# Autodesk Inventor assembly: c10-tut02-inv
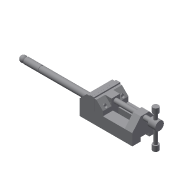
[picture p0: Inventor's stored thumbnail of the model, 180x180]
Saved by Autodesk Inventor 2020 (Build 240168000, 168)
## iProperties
Created: 2009-05
Part Number: c10-tut02-inv
Document SubType Name: Assembly
Designer: Sham
Author: Sham
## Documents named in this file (9)
- D:\Autodesk Inventor_2020\Resources1\c10\c10_Inv_2019_tut\c10_Inv_tut_2019\c10_tut02_inv\Drill Press Vice\Drill Press Vice Assembly.iam
- D:\Autodesk Inventor_2020\Resources1\c10\c10_Inv_2019_tut\c10_Inv_tut_2019\c10_tut02_inv\Drill Press Vice\Base.ipt
- D:\Autodesk Inventor_2020\Resources1\c10\c10_Inv_2019_tut\c10_Inv_tut_2019\c10_tut02_inv\Drill Press Vice\Safety Handle.ipt
- D:\Autodesk Inventor_2020\Resources1\c10\c10_Inv_2019_tut\c10_Inv_tut_2019\c10_tut02_inv\Drill Press Vice\Jaw Face.ipt
- D:\Autodesk Inventor_2020\Resources1\c10\c10_Inv_2019_tut\c10_Inv_tut_2019\c10_tut02_inv\Drill Press Vice\Movable Jaw.ipt
- D:\Autodesk Inventor_2020\Resources1\c10\c10_Inv_2019_tut\c10_Inv_tut_2019\c10_tut02_inv\Drill Press Vice\Cap Screw.ipt
- D:\Autodesk Inventor_2020\Resources1\c10\c10_Inv_2019_tut\c10_Inv_tut_2019\c10_tut02_inv\Drill Press Vice\Clamp Screw Handle.ipt
- D:\Autodesk Inventor_2020\Resources1\c10\c10_Inv_2019_tut\c10_Inv_tut_2019\c10_tut02_inv\Drill Press Vice\Clamp Screw.ipt
- D:\Autodesk Inventor_2020\Resources1\c10\c10_Inv_2019_tut\c10_Inv_tut_2019\c10_tut02_inv\Drill Press Vice\Handle Stop.ipt
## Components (11 placed, 8 different names)
1. Base:1 — Mate:1, Flush:1, Insert:1, Insert:2, Insert:3
2. Movable Jaw:1 — Mate:1, Flush:1, Insert:4, Insert:5, Insert:6, Insert:7, Insert:8
3. Safety Handle:1 — Insert:1
4. Jaw Face:1 — Insert:4, Insert:5, Mate:7
5. Jaw Face:2 — Insert:2, Insert:3, Mate:7
6. Cap Screw:1 — Insert:7
7. Cap Screw:2 — Insert:6
8. Clamp Screw:1 — Insert:8, Mate:2
9. Clamp Screw Handle:1 — Mate:2, Insert:9, Insert:10
10. Handle Stop:1 — Insert:10
11. Handle Stop:2 — Insert:9
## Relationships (14: Insert 10, Mate 3, Flush 1)
- Mate:1: Base:1 ↔ Movable Jaw:1
- Flush:1: Base:1 ↔ Movable Jaw:1
- Insert:1: Base:1 ↔ Safety Handle:1
- Insert:2: Base:1 ↔ Jaw Face:2
- Insert:3: Base:1 ↔ Jaw Face:2
- Insert:4: Movable Jaw:1 ↔ Jaw Face:1
- Insert:5: Movable Jaw:1 ↔ Jaw Face:1
- Insert:6: Movable Jaw:1 ↔ Cap Screw:2
- Insert:7: Movable Jaw:1 ↔ Cap Screw:1
- Insert:8: Movable Jaw:1 ↔ Clamp Screw:1
- Mate:2: Clamp Screw:1 ↔ Clamp Screw Handle:1
- Insert:9: Clamp Screw Handle:1 ↔ Handle Stop:2
- Insert:10: Clamp Screw Handle:1 ↔ Handle Stop:1
- Mate:7: Jaw Face:1 ↔ Jaw Face:2
